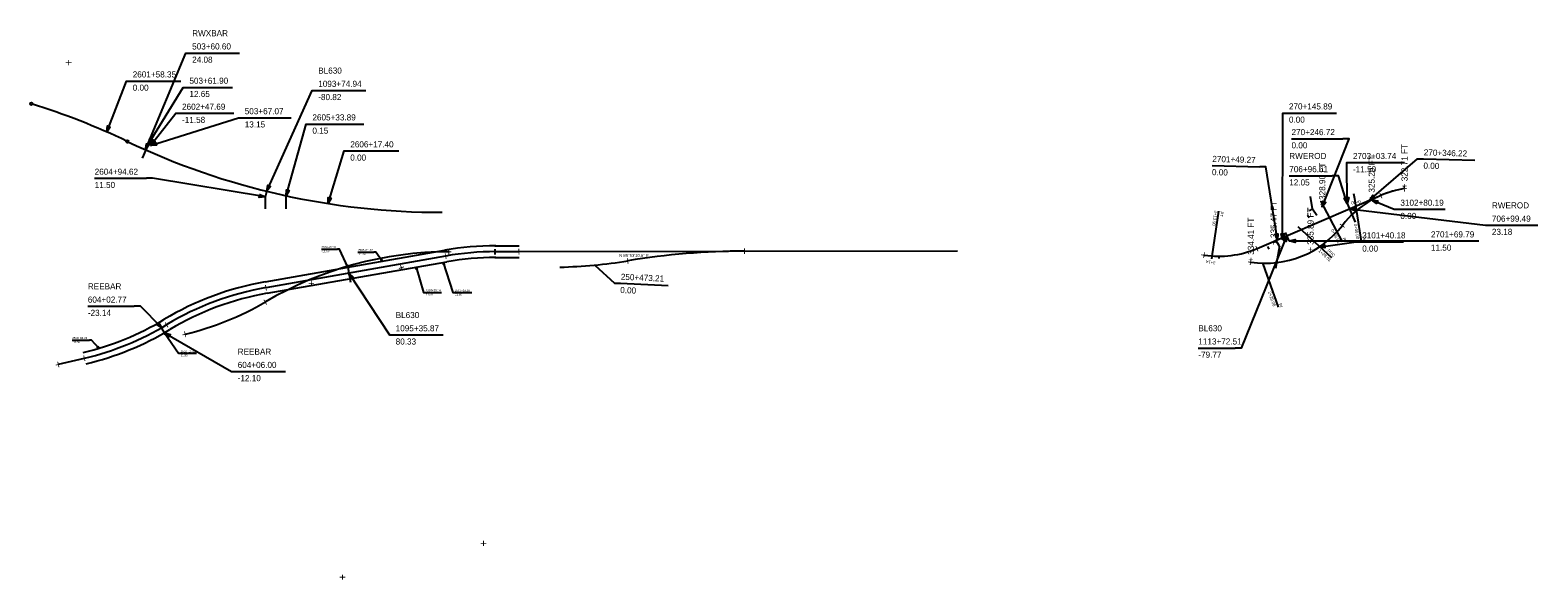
# Model space of a CAD drawing. Extents: x 1195880 to 1289360, y 2059330 to 2086925.
# Drawn here: x 1200685 to 1203650, y 2068855 to 2069936 of the extents above; entities that cross this region are included whole.
import ezdxf

# ---------------------------------------------------------------- set-up
doc = ezdxf.new("R2010")
doc.units = 0
for name, color, linetype in [('20', 7, 'Continuous'), ('3', 7, 'Continuous'), ('5', 7, 'Continuous'), ('9', 7, 'Continuous'), ('Default', 7, 'Continuous'), ('Prop Ramp 100 Scale PCPT', 7, 'Continuous'), ('Prop Ramp 100 Scale PI', 7, 'Continuous'), ('Prop Ramp 100 Scale Sta', 7, 'Continuous'), ('Prop_Horiz Alignment', 7, 'Continuous'), ('Step 2 BL', 7, 'Continuous')]:
    doc.layers.add(name, color=color, linetype=linetype)

msp = doc.modelspace()

# ---------------------------------------------------------------- linework, layer by layer
for p, q in [((1201003.4, 2069890.8), (1201096.5, 2069890.8)), ((1200886.6, 2069835.8), (1200981.1, 2069835.8)), ((1200998.1, 2069823.4), (1201082.8, 2069823.4)), ((1201251.4, 2069817.3), (1201345.4, 2069817.3)), ((1200983.6, 2069772.4), (1201085.5, 2069772.4)), ((1203160.6, 2069772.9), (1203254.6, 2069772.9)), ((1201106.9, 2069763.5), (1201198.3, 2069763.5)), ((1201239.9, 2069751.3), (1201341.3, 2069751.3)), ((1203165.8, 2069722.4), (1203267.1, 2069722.4)), ((1201314.4, 2069698.3), (1201410.5, 2069698.3)), ((1203425.5, 2069682.6), (1203526.8, 2069679.9)), ((1203009.6, 2069669.8), (1203103.5, 2069667.3)), ((1203161.3, 2069649.5), (1203246.1, 2069649.5)), ((1203286.6, 2069675.4), (1203388.2, 2069675.4)), ((1200811.7, 2069644.5), (1200913.6, 2069644.5)), ((1203379.8, 2069583.6), (1203468, 2069583.6)), ((1203559.8, 2069552.3), (1203650.5, 2069552.3)), ((1201258, 2069505.3), (1201289.8, 2069505.3)), ((1203304.8, 2069519.4), (1203386, 2069519.4)), ((1203439.9, 2069521.3), (1203534.5, 2069521.3)), ((1201329.7, 2069499.5), (1201361.2, 2069499.5)), ((1201462.9, 2069420.2), (1201494.2, 2069420.2)), ((1201520.1, 2069419.9), (1201554, 2069419.9)), ((1201846.1, 2069438.1), (1201939.9, 2069434)), ((1200798.3, 2069393.1), (1200889.8, 2069393.1)), ((1200767.6, 2069326.6), (1200801.7, 2069326.6)), ((1201403.7, 2069336.7), (1201497.6, 2069336.7)), ((1200980.8, 2069300.5), (1201012.3, 2069300.5)), ((1202982.5, 2069310.8), (1203055, 2069310.8)), ((1201093, 2069264.7), (1201187.1, 2069264.7))]:
    msp.add_line(p, q)
for points in [[(1200912.2, 2069700.4), (1200991.4, 2069890.8), (1201003.4, 2069890.8)], [(1200835.8, 2069735.5), (1200874.6, 2069835.8), (1200886.6, 2069835.8)], [(1200916.9, 2069711), (1200986.1, 2069823.4), (1200998.1, 2069823.4)], [(1201150.5, 2069619.1), (1201239.4, 2069817.3), (1201251.4, 2069817.3)], [(1200921.6, 2069708.9), (1200971.6, 2069772.4), (1200983.6, 2069772.4)], [(1203148.4, 2069523.9), (1203148.6, 2069772.9), (1203160.6, 2069772.9)], [(1200921.6, 2069708.9), (1201094.9, 2069763.5), (1201106.9, 2069763.5)], [(1201188.8, 2069610.1), (1201227.9, 2069751.3), (1201239.9, 2069751.3)], [(1203226.2, 2069587.5), (1203279.1, 2069722.4), (1203267.1, 2069722.4)], [(1201270.9, 2069594.9), (1201302.4, 2069698.3), (1201314.4, 2069698.3)], [(1203319.2, 2069601.3), (1203413.5, 2069682.9), (1203425.5, 2069682.6)], [(1203138.2, 2069523.8), (1203115.5, 2069667), (1203103.5, 2069667.3)], [(1203275.7, 2069595.1), (1203258.1, 2069649.5), (1203246.1, 2069649.5)], [(1203275.7, 2069595.1), (1203274.6, 2069675.4), (1203286.6, 2069675.4)], [(1201147.8, 2069607.9), (1200925.6, 2069644.5), (1200913.6, 2069644.5)], [(1203323.6, 2069601.9), (1203367.8, 2069583.6), (1203379.8, 2069583.6)], [(1203280.2, 2069584.5), (1203547.8, 2069552.3), (1203559.8, 2069552.3)], [(1203157, 2069531.9), (1203067, 2069310.8), (1203055, 2069310.8)], [(1201309.8, 2069469.6), (1201293.8, 2069505.3), (1201289.8, 2069505.3)], [(1203161.6, 2069521.3), (1203427.9, 2069521.3), (1203439.9, 2069521.3)], [(1203219.8, 2069509.1), (1203292.8, 2069519.4), (1203304.8, 2069519.4)], [(1201377.6, 2069481.5), (1201365.2, 2069499.5), (1201361.2, 2069499.5)], [(1201497.7, 2069479.2), (1201516.1, 2069419.9), (1201520.1, 2069419.9)], [(1201795.8, 2069473.9), (1201834.1, 2069438.6), (1201846.1, 2069438.1)], [(1201311.8, 2069458.2), (1201391.7, 2069336.7), (1201403.7, 2069336.7)], [(1201444.4, 2069469.8), (1201458.9, 2069420.2), (1201462.9, 2069420.2)], [(1200943.6, 2069350.9), (1200901.8, 2069393.1), (1200889.8, 2069393.1)], [(1200820, 2069310.4), (1200805.7, 2069326.6), (1200801.7, 2069326.6)], [(1200949.3, 2069340.9), (1200976.8, 2069300.5), (1200980.8, 2069300.5)], [(1200949.3, 2069340.9), (1201081, 2069264.7), (1201093, 2069264.7)]]:
    msp.add_lwpolyline(points)
for points in [[(1200835.8, 2069735.5), (1200837.2, 2069747.4), (1200842.7, 2069745.3)], [(1200912.2, 2069700.4), (1200914, 2069712.3), (1200919.4, 2069710.1)], [(1200916.9, 2069711), (1200920.5, 2069722.4), (1200925.4, 2069719.4)], [(1200921.6, 2069708.9), (1200926.5, 2069719.9), (1200931.1, 2069716.3)], [(1200921.6, 2069708.9), (1200931.9, 2069715.2), (1200933.6, 2069709.7)], [(1201150.5, 2069619.1), (1201152.6, 2069630.9), (1201157.9, 2069628.5)], [(1201188.8, 2069610.1), (1201189.1, 2069622.1), (1201194.7, 2069620.5)], [(1201147.8, 2069607.9), (1201135.8, 2069606.9), (1201136.8, 2069612.7)], [(1201270.9, 2069594.9), (1201271.5, 2069606.9), (1201277, 2069605.2)], [(1203226.2, 2069587.5), (1203227.7, 2069599.4), (1203233.2, 2069597.2)], [(1203275.7, 2069595.1), (1203269.3, 2069605.3), (1203274.9, 2069607.1)], [(1203275.7, 2069595.1), (1203272.6, 2069606.7), (1203278.4, 2069606.8)], [(1203319.2, 2069601.3), (1203326.1, 2069611.1), (1203330, 2069606.7)], [(1203323.6, 2069601.9), (1203335.5, 2069600.1), (1203333.2, 2069594.8)], [(1203280.2, 2069584.5), (1203292.1, 2069586), (1203291.4, 2069580.3)], [(1203138.2, 2069523.8), (1203133.5, 2069534.8), (1203139.2, 2069535.7)], [(1203148.4, 2069523.9), (1203145.5, 2069535.5), (1203151.3, 2069535.5)], [(1203157, 2069531.9), (1203155.3, 2069520), (1203150, 2069522.2)], [(1203161.6, 2069521.3), (1203173.2, 2069524.2), (1203173.2, 2069518.4)], [(1203219.8, 2069509.1), (1203231, 2069513.6), (1203231.8, 2069507.9)], [(1201309.8, 2069469.6), (1201307.3, 2069472.7), (1201309.1, 2069473.5)], [(1201377.6, 2069481.5), (1201374.6, 2069484.1), (1201376.2, 2069485.2)], [(1201497.7, 2069479.2), (1201499.8, 2069475.8), (1201498, 2069475.2)], [(1201311.8, 2069458.2), (1201320.6, 2069450.1), (1201315.7, 2069446.9)], [(1201444.4, 2069469.8), (1201446.4, 2069466.4), (1201444.6, 2069465.8)], [(1200943.6, 2069350.9), (1200933.4, 2069357.1), (1200937.5, 2069361.2)], [(1200949.3, 2069340.9), (1200952.3, 2069338.3), (1200950.7, 2069337.2)], [(1200949.3, 2069340.9), (1200960.9, 2069337.6), (1200958, 2069332.6)], [(1200820, 2069310.4), (1200816.7, 2069312.7), (1200818.2, 2069314)]]:
    msp.add_lwpolyline(points, close=True)
at = {"layer": '20'}
for p, q in [((1203098.3, 2069506.7), (1203342.1, 2069611.1)), ((1201149.3, 2069429.7), (1201502.9, 2069491.8)), ((1201599.1, 2069500.4), (1201646.9, 2069500.5)), ((1201599.1, 2069500.4), (1201646.9, 2069500.5)), ((1200741.1, 2069278.9), (1200792.2, 2069291.1)), ((1200741.1, 2069278.9), (1200792.2, 2069291.1))]:
    msp.add_line(p, q, dxfattribs=at)
for centre, radius, start, end in [((1203417.3, 2069435.5), 191, 98.7484, 113.1607), ((1203023.2, 2069682.3), 191, 261.3825, 293.1607), ((1201601.9, 2068927.4), 573, 90.1137, 99.9515), ((1201248.3, 2068865.4), 573, 99.9515, 120.922), ((1200659.5, 2069848.4), 573, 283.3963, 300.922), ((1200659.5, 2069848.4), 573, 283.3963, 300.922)]:
    msp.add_arc(centre, radius, start, end, dxfattribs=at)
at = {"layer": '5'}
for centre, radius, start, end in [((1203417.3, 2069435.5), 191, 98.7484, 142.4046), ((1203114.6, 2069668.5), 191, 261.3825, 322.4046), ((1202093.6, 2068069), 1432.4, 90.1137, 99.3489), ((1201510.5, 2068784), 716.2, 90.1137, 120.4238), ((1201705.8, 2070424.6), 954.9, 271.2697, 279.3489), ((1200857.7, 2069895.7), 573, 283.3971, 300.4238)]:
    msp.add_arc(centre, radius, start, end, dxfattribs=at)
at = {"layer": 'Default'}
for p, q in [((1200916.9, 2069711), (1200905.1, 2069684.4)), ((1201147.8, 2069607.9), (1201151.7, 2069623.7)), ((1203207.1, 2069584.4), (1203203.4, 2069608.7)), ((1203275.7, 2069595.1), (1203291.4, 2069558.3)), ((1203201.1, 2069580.3), (1203207.1, 2069584.4)), ((1203207.1, 2069584.4), (1203215.6, 2069572.2)), ((1203161.6, 2069521.3), (1203154.4, 2069538.1)), ((1201147.3, 2069441.1), (1201500.9, 2069503.1)), ((1201599, 2069511.9), (1201646.9, 2069512)), ((1201608.7, 2069500.4), (1202508.7, 2069502.2)), ((1203142.4, 2069510.9), (1203134.6, 2069523.7)), ((1203142.4, 2069510.9), (1203134.7, 2069467.3)), ((1201151.3, 2069418.4), (1201504.9, 2069480.5)), ((1201599.1, 2069488.9), (1201647, 2069489)), ((1201309.8, 2069469.6), (1201314.9, 2069440.4)), ((1200949.3, 2069340.9), (1200938.9, 2069359.2))]:
    msp.add_line(p, q, dxfattribs=at)
for centre, radius, start, end in [((1200259.7, 2068424.1), 1432.4, 64.5137, 72.6197), ((1201492.4, 2071010.1), 1432.4, 244.5137, 270.1137), ((1201601.9, 2068927.4), 584.5, 90.1137, 99.9515), ((1201601.9, 2068927.4), 561.5, 90.1137, 99.9515), ((1201248.3, 2068865.4), 584.5, 99.9515, 120.922), ((1201248.3, 2068865.4), 561.5, 99.9515, 120.922), ((1200659.5, 2069848.4), 561.5, 283.3963, 300.922), ((1200659.5, 2069848.4), 584.5, 283.3963, 300.922)]:
    msp.add_arc(centre, radius, start, end, dxfattribs=at)
at = {"layer": 'Prop Ramp 100 Scale PCPT'}
for points in [[(1203289.5, 2069609), (1203303.1, 2069520.1)], [(1203009.9, 2069491.2), (1203023.3, 2069580.2)], [(1203178.5, 2069550.1), (1203244.5, 2069488.9)]]:
    msp.add_lwpolyline(points, dxfattribs=at)
at = {"layer": 'Prop Ramp 100 Scale PI'}
for points in [[(1203223.7, 2069598.9), (1203223.7, 2069598.9), (1203265.9, 2069519.4)], [(1203109.8, 2069476.1), (1203109.8, 2069476.1), (1203139.5, 2069391.1)]]:
    msp.add_lwpolyline(points, dxfattribs=at)
at = {"layer": 'Prop Ramp 100 Scale Sta'}
for points in [[(1203290.2, 2069604.1), (1203288.7, 2069614)], [(1203200.7, 2069567.1), (1203197.2, 2069571.4)], [(1203122, 2069505.2), (1203119.7, 2069510.2)], [(1203009.1, 2069486.3), (1203010.6, 2069496.1)], [(1203009.1, 2069486.3), (1203010.6, 2069496.1)], [(1203023.4, 2069486.9), (1203023.9, 2069492.4)]]:
    msp.add_lwpolyline(points, dxfattribs=at)
at = {"layer": 'Prop_Horiz Alignment'}
for centre in [(1200687.5, 2069791.1), (1200876, 2069717.1)]:
    msp.add_circle(centre, 2.5, dxfattribs=at)
at = {"layer": 'Step 2 BL'}
for p, q in [((1201147.8, 2069584.4), (1201147.8, 2069607.9)), ((1201188.8, 2069584.6), (1201188.8, 2069610.1))]:
    msp.add_line(p, q, dxfattribs=at)

# ---------------------------------------------------------------- texts
at = {"layer": '20'}
for s, height, p in [('RWXBAR', 12, (1201003.7, 2069923.8)), ('503+60.60', 12, (1201003.7, 2069897.8)), ('24.08', 12, (1201003.7, 2069871.8)), ('BL630', 12, (1201251.7, 2069850.3)), ('0.00', 12, (1200886.8, 2069816.8)), ('2601+58.35', 12, (1200886.8, 2069842.8)), ('503+61.90', 12, (1200998.3, 2069830.4)), ('1093+74.94', 12, (1201251.7, 2069824.3)), ('12.65', 12, (1200998.3, 2069804.4)), ('-80.82', 12, (1201251.7, 2069798.3)), ('2602+47.69', 12, (1200983.8, 2069779.4)), ('503+67.07', 12, (1201107.1, 2069770.5)), ('2605+33.89', 12, (1201240.2, 2069758.3)), ('270+145.89', 12, (1203160.9, 2069779.9)), ('-11.58', 12, (1200983.8, 2069753.4)), ('13.15', 12, (1201107.1, 2069744.5)), ('0.15', 12, (1201240.2, 2069732.3)), ('0.00', 12, (1203160.9, 2069753.9)), ('270+246.72', 12, (1203166, 2069729.4)), ('2606+17.40', 12, (1201314.7, 2069705.3)), ('0.00', 12, (1203166, 2069703.4)), ('0.00', 12, (1201314.7, 2069679.3)), ('RWEROD', 12, (1203161.5, 2069682.5)), ('2703+03.74', 12, (1203286.8, 2069682.4)), ('2604+94.62', 12, (1200812, 2069651.5)), ('706+96.61', 12, (1203161.5, 2069656.5)), ('-11.50', 12, (1203286.8, 2069656.4)), ('11.50', 12, (1200812, 2069625.5)), ('12.05', 12, (1203161.5, 2069630.5)), ('3102+80.19', 12, (1203380.1, 2069590.6)), ('RWEROD', 12, (1203560.1, 2069585.3)), ('0.00', 12, (1203380.1, 2069564.6)), ('706+99.49', 12, (1203560.1, 2069559.3)), ('3101+40.18', 12, (1203305, 2069526.4)), ('2701+69.79', 12, (1203440.2, 2069528.3)), ('23.18', 12, (1203560.1, 2069533.3)), ('-11.50', 4, (1201258.3, 2069499.3)), ('2506+02.51', 4, (1201258.3, 2069507.3)), ('2506+71.32', 4, (1201329.9, 2069501.5)), ('0.00', 12, (1203305, 2069500.4)), ('11.50', 12, (1203440.2, 2069502.3)), ('-11.50', 4, (1201329.9, 2069493.5)), ('604+02.77', 12, (1200798.5, 2069400.1)), ('REEBAR', 12, (1200798.5, 2069426.1)), ('2507+35.14', 4, (1201463.1, 2069422.2)), ('11.50', 4, (1201463.1, 2069414.2)), ('2507+89.30', 4, (1201520.4, 2069421.9)), ('11.50', 4, (1201520.4, 2069413.9)), ('-23.14', 12, (1200798.5, 2069374.1)), ('1095+35.87', 12, (1201404, 2069343.7)), ('BL630', 12, (1201404, 2069369.7)), ('BL630', 12, (1202982.7, 2069343.8)), ('2500+84.76', 4, (1200767.9, 2069328.6)), ('-11.50', 4, (1200767.9, 2069320.6)), ('80.33', 12, (1201404, 2069317.7)), ('1113+72.51', 12, (1202982.7, 2069317.8)), ('2502+15.96', 4, (1200981, 2069302.5)), ('11.50', 4, (1200981, 2069294.5)), ('REEBAR', 12, (1201093.3, 2069297.7)), ('-79.77', 12, (1202982.7, 2069291.8)), ('604+06.00', 12, (1201093.3, 2069271.7)), ('-12.10', 12, (1201093.3, 2069245.7))]:
    msp.add_text(s, height=height, dxfattribs=at).set_placement(p)
for s, height, rotation, p in [('+', 16, 90, (1200768.5, 2069865.5)), ('2701+49.27', 12, 358.4775, (1203010.1, 2069676.8)), ('270+346.22', 12, 358.4775, (1203426, 2069689.6)), ('0.00', 12, 358.4775, (1203009.4, 2069650.8)), ('0.00', 12, 358.4775, (1203425.3, 2069663.6)), ('+', 16, 8.7484, (1203382.6, 2069615.3)), ('+', 16, 8.7484, (1203382.6, 2069615.3)), ('+', 16, 23.1607, (1203339, 2069601)), ('+', 16, 52.4046, (1203268.1, 2069541.7)), ('+', 16, 0.1137, (1201502.3, 2069492.2)), ('+', 16, 0.1137, (1201592.2, 2069492.4)), ('+', 16, 0.1137, (1201592.2, 2069492.4)), ('+', 16, 0.1137, (1201594, 2069492.4)), ('+', 16, 0.1137, (1201594, 2069492.4)), ('+', 16, 0.1137, (1201640.1, 2069492.5)), ('+', 16, 0.1137, (1201640.1, 2069492.5)), ('+', 16, 0.1137, (1202083.9, 2069493.4)), ('+', 16, 23.1607, (1203095.2, 2069496.7)), ('+', 16, 18.9641, (1201411.8, 2069459.5)), ('+', 16, 9.9515, (1201497.5, 2069482.7)), ('+', 16, 9.3489, (1201855.4, 2069473.3)), ('+', 16, 351.3825, (1202986.6, 2069486.6)), ('+', 16, 351.3825, (1203078, 2069472.8)), ('+', 16, 0.9389, (1201232.2, 2069430.2)), ('250+473.21', 12, 357.5164, (1201846.6, 2069445.1)), ('+', 16, 9.9515, (1201143.9, 2069420.7)), ('0.00', 12, 357.5164, (1201845.5, 2069419.1)), ('+', 16, 30.4238, (1201146, 2069391.2)), ('+', 16, 30.922, (1200952.1, 2069346.5)), ('+', 16, 30.922, (1200952.1, 2069346.5)), ('+', 16, 13.3971, (1200985.6, 2069328.9)), ('+', 16, 13.3963, (1200787.4, 2069281.7)), ('+', 16, 13.3963, (1200787.4, 2069281.7)), ('+', 16, 13.3963, (1200736.2, 2069269.5)), ('+', 16, 13.3963, (1200736.2, 2069269.5)), ('+', 16, 90, (1201584.4, 2068920.5)), ('+', 16, 90, (1201307.1, 2068854.1))]:
    msp.add_text(s, height=height, rotation=rotation, dxfattribs=at).set_placement(p)
at = {"layer": '3'}
msp.add_text('N 89%%d53\'10.6" E', height=6, rotation=0.1137, dxfattribs=at).set_placement((1201843.4, 2069489.9))
at = {"layer": '9'}
for s, p in [(' + 322.71 FT', (1203394.2, 2069620.4)), (' + 325.29 FT', (1203329.6, 2069598.1)), (' + 328.90 FT', (1203232.4, 2069583.8)), (' + 335.47 FT', (1203136.7, 2069508.9)), (' + 334.41 FT', (1203092, 2069475.8)), (' + 335.89 FT', (1203209.4, 2069495.5))]:
    msp.add_text(s, height=12, rotation=90, dxfattribs=at).set_placement(p)
at = {"layer": 'Prop Ramp 100 Scale PCPT'}
for s, rotation, p in [('3+13.90', 261.3825, (1203014.4, 2069581.5)), ('PT ', 261.3825, (1203026.3, 2069579.7)), ('0+00.00', 278.7484, (1203288.8, 2069554.4)), ('1+28.01', 317.1506, (1203218.3, 2069501)), ('PRC ', 317.1506, (1203235.5, 2069501.4)), ('PC ', 278.7484, (1203304.7, 2069529.8))]:
    msp.add_text(s, height=6, rotation=rotation, dxfattribs=at).set_placement(p)
at = {"layer": 'Prop Ramp 100 Scale PI'}
for s, rotation, p in [('0+66.51', 297.9495, (1203243.2, 2069542.9)), ('PI ', 297.9495, (1203265.9, 2069525.8)), ('2+29.06', 289.2666, (1203119.6, 2069420.7)), ('PI ', 289.2666, (1203140.4, 2069397.4))]:
    msp.add_text(s, height=6, rotation=rotation, dxfattribs=at).set_placement(p)
at = {"layer": 'Prop Ramp 100 Scale Sta'}
for s, rotation, p in [('0+00', 188.7484, (1203301.5, 2069601.8)), ('3+14', 171.3825, (1203016.7, 2069481.1)), ('3+14', 171.3825, (1203016.7, 2069481.1))]:
    msp.add_text(s, height=6, rotation=rotation, dxfattribs=at).set_placement(p)

doc.saveas('drawing.dxf')
